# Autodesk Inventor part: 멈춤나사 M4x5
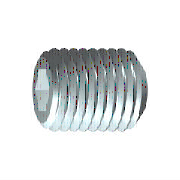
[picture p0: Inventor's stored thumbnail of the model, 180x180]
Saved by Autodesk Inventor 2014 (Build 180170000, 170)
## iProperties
Created: 2012-02
Part Number: 멈춤나사 M4x5
Material: 강철, 연강
Description: 6각 소켓 머리 없는 멈춤 나사
Document SubType Name: Modeling
Standard: KS B 1028
Designer: mduedu
Standards Organization: KS
Language: ko-KR
Size Designation: 납작점M4x5
Categories: <MemberInstance><Categories><Category DisplayName="조임쇠" InternalName="e4da775c-781d-43d5-af7c-5136215cf5a6" Mnemonic="FSTN"><Category DisplayName="볼트" InternalN
Density: 1 g/cm^3
Appearance: Steel
IsCustomPart: 1
Author: mduedu
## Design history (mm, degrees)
sketch "스케치1"
  geometry: L1 (0, 0)-(1.833, 0); L2 (5, 1.155)-(5, 2); L3 (5, 2)-(0, 2); L4 (5, 1.155)-(2.5, 1.155); L5 (2.5, 1.155)-(1.833, 0); L6 (0, -0.4)-(0, 2.4) reference; L7 (0, 2)-(0, 0)
  constraints: 13 end point, 3 parallel, 1 collinear, 1 perpendicular, 1 point on line
  dimensions: "d0" = 2.5 distance of L2.start L4.end (= INTI); "d1" = 60 deg angle of L5 L1; "d2" = 4 diameter of L3 L1 (= NND); "d3" = 2.3094 diameter of L4 L1 (= 1.1547 x SW); "d5" = 5 distance from line of L2 L3.end (= NLG)
revolve "본체" sketch "스케치1" stored, may be unused: angle "d6" = 90 deg
sketch "스케치2"
  geometry: L1 (-0.577, 1)-(0.577, 1); L2 (0.577, 1)-(1.155, 0); L3 (1.155, 0)-(0.577, -1); L4 (0.577, -1)-(-0.577, -1); L5 (-0.577, -1)-(-1.155, 0); L6 (-1.155, 0)-(-0.577, 1); A1 r 1.155 centre (0, 0) between (-0.577, 1) and (0.577, 1) reference; 2 further points
  constraints: 12 end point, 2 point on circle, 1 coincident, 1 horizontal, 11 other
extrude "슬롯" join sketch "스케치2" taper "d9" = 0 deg; stored distance "d21" = 10
workaxis "Work Axis1"
workplane "Work Plane1"
workpoint "Work Point1"
  workaxis "Work Axis4"
body "Solid1"
chamfer "모따기1" distance "d7" = 0.42941 (= -0.5 x GD1 + 0.5 x NND); stored, may be unused: angle "d8" = 45 deg (= FAWI), second distance "d29" = 0.42941 (= -0.5 x GD1 + 0.5 x NND)
feature "스레드" dims "d11" = 5 (= NLG), "d12" = 0
chamfer "모따기2" distance "d13" = 0.42941 (= -0.5 x GD1 + 0.5 x NND); stored, may be unused: angle "d14" = 45 deg (= FAWI), second distance "d30" = 0.42941 (= -0.5 x GD1 + 0.5 x NND)
other parameters: "NND" = 4 [user parameter; used in 5 equation terms], "NLG" = 5 [user parameter; used in 2 equation terms], "INTI" = 2.5 [user parameter; used in 1 equation term], "FAWI" = 45 deg [user parameter; used in 2 equation terms], "SW" = 2 [user parameter; used in 2 equation terms], "GD1" = 3.14117 (= THREADDIA - 1.2269 x PTC) [user parameter; used in 4 equation terms], "d4" = 0, "FAWI1" = 45 deg [user parameter], "d15" = 0, "d31" = 0, "GUL" = 0.42941 (= 0.61345 x PTC) [user parameter], "SPD" = 2.5 [user parameter], "TPU" = 14.28571 (computed from PTC) [user parameter], "TOA" = 30 deg [user parameter], "THREADDIA" = 4 [user parameter; used in 1 equation term], "PTC" = 0.7 [user parameter; used in 4 equation terms], "GAL" = 0.42941 (= 0.61345 x PTC) [user parameter], "E0" = 2.31 (= 1.155 x SW) [user parameter]
